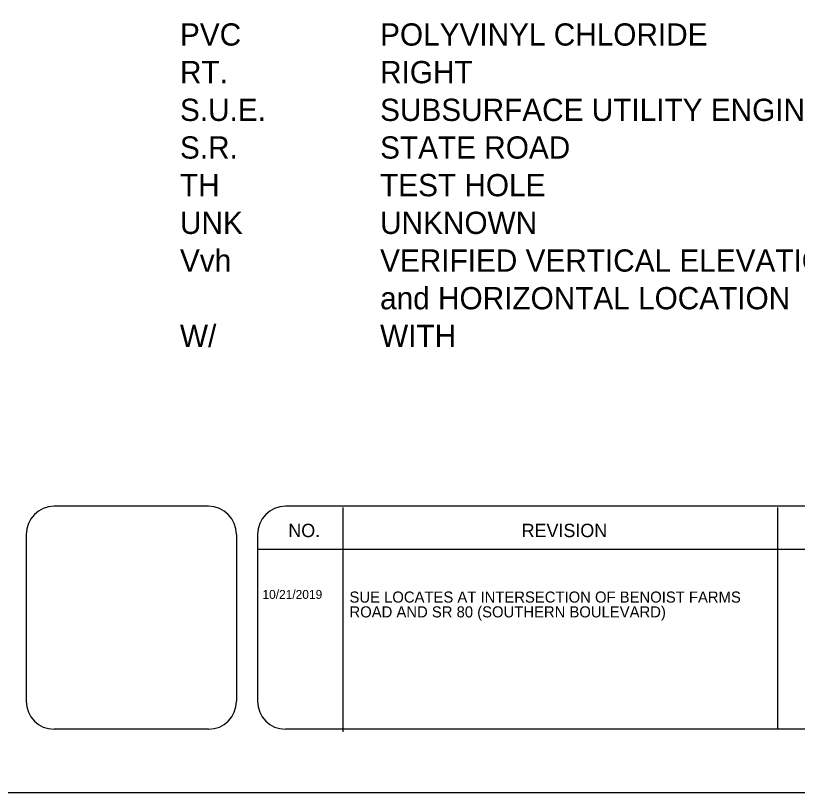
# Model space of a CAD drawing. Extents: x -769.4 to -731.2, y -2181.6 to -2171.
# Drawn here: x -742.954 to -740.495, y -2181.581 to -2179.138 of the extents above; entities that cross this region are included whole.
import ezdxf

# ---------------------------------------------------------------- set-up
doc = ezdxf.new("R2010")
doc.units = 0
for name, color, linetype in [('Default', 7, 'Continuous'), ('PlotBorder_dp', 7, 'Continuous'), ('TextSurveyLabel', 7, 'Continuous')]:
    doc.layers.add(name, color=color, linetype=linetype)

msp = doc.modelspace()

# ---------------------------------------------------------------- linework, layer by layer
at = {"layer": 'Default'}
for p, q in [((-742.3478, -2180.6815), (-742.833, -2180.6815)), ((-740.0763, -2180.6815), (-742.1052, -2180.6815)), ((-741.9252, -2180.685), (-741.9252, -2181.3908)), ((-740.558, -2180.685), (-740.558, -2181.3819)), ((-742.9212, -2180.7697), (-742.9212, -2181.2946)), ((-742.2596, -2180.7697), (-742.2596, -2181.2946)), ((-742.1935, -2180.7697), (-742.1935, -2181.2946)), ((-739.9846, -2180.8174), (-742.1899, -2180.8174)), ((-742.3478, -2181.3828), (-742.833, -2181.3828)), ((-740.0763, -2181.3828), (-742.1052, -2181.3828))]:
    msp.add_line(p, q, dxfattribs=at)
for centre, major_axis, start_param, end_param in [((-742.833, -2180.7697), (0, 0.0882), 0, 1.570796), ((-742.3478, -2180.7697), (0, 0.0882), 4.712389, 6.283185), ((-742.1052, -2180.7697), (0, 0.0882), 0, 1.570796), ((-742.833, -2181.2946), (0, -0.0882), 4.712389, 6.283185), ((-742.3478, -2181.2946), (0, 0.0882), 3.141593, 4.712389), ((-742.1052, -2181.2946), (0, -0.0882), 4.712389, 6.283185)]:
    msp.add_ellipse(centre, major_axis=major_axis, ratio=0.999927, start_param=start_param, end_param=end_param, dxfattribs=at)
at = {"layer": 'PlotBorder_dp'}
msp.add_lwpolyline([(-749.1334, -2181.5815), (-732.6334, -2181.5815), (-732.6334, -2170.9815), (-749.1334, -2170.9815)], close=True, dxfattribs=at)

# ---------------------------------------------------------------- texts
at = {"layer": 'Default'}
for s, p in [('NO.', (-742.0965, -2180.7785)), ('REVISION', (-741.3625, -2180.7785))]:
    msp.add_text(s, height=0.04207, dxfattribs=at).set_placement(p)
at = {"layer": 'TextSurveyLabel'}
for s, p in [('PVC', (-742.4374, -2179.2319)), ('POLYVINYL CHLORIDE', (-741.8079, -2179.2319)), ('RT.', (-742.4374, -2179.3504)), ('RIGHT', (-741.8079, -2179.3504)), ('S.U.E.', (-742.4374, -2179.469)), ('SUBSURFACE UTILITY ENGINEERING', (-741.8079, -2179.469)), ('S.R.', (-742.4374, -2179.5875)), ('STATE ROAD', (-741.8079, -2179.5875)), ('TH', (-742.4374, -2179.706)), ('TEST HOLE', (-741.8079, -2179.706)), ('UNK', (-742.4374, -2179.8245)), ('UNKNOWN', (-741.8079, -2179.8245)), ('Vvh', (-742.4374, -2179.9431)), ('VERIFIED VERTICAL ELEVATION', (-741.8079, -2179.9431)), ('and HORIZONTAL LOCATION', (-741.8079, -2180.0616)), ('W/', (-742.4374, -2180.1801)), ('WITH', (-741.8079, -2180.1801))]:
    msp.add_text(s, height=0.07, rotation=360, dxfattribs=at).set_placement(p)
for s, height, p in [('10/21/2019', 0.02808, (-742.1779, -2180.9727)), ('SUE LOCATES AT INTERSECTION OF BENOIST FARMS ', 0.034881, (-741.9042, -2180.9844)), ('ROAD AND SR 80 (SOUTHERN BOULEVARD)', 0.034881, (-741.9042, -2181.031))]:
    msp.add_text(s, height=height, dxfattribs=at).set_placement(p)

doc.saveas('drawing.dxf')
